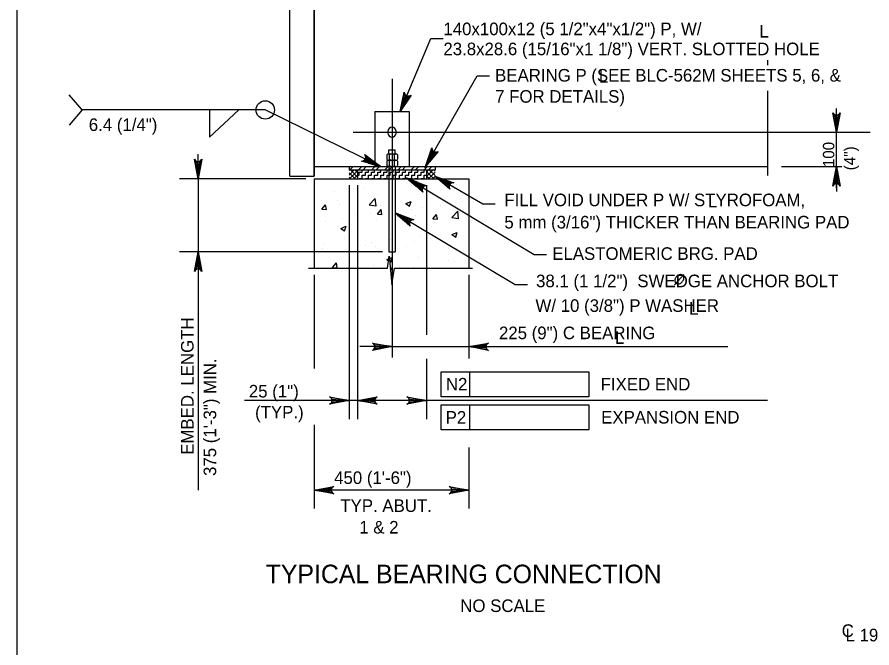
# Model space of a CAD drawing. Extents: x 638263 to 640360, y 293683 to 298655.
# Drawn here: x 639316.5 to 639520.4, y 298195.5 to 298346 of the extents above; entities that cross this region are included whole.
import ezdxf

# ---------------------------------------------------------------- set-up
doc = ezdxf.new("R2010")
doc.units = 0
for name, color, linetype in [('2', 7, 'Continuous'), ('3', 7, 'Continuous'), ('4', 7, 'Continuous'), ('5', 7, 'Continuous')]:
    doc.layers.add(name, color=color, linetype=linetype)

msp = doc.modelspace()

# ---------------------------------------------------------------- linework, layer by layer
at = {"layer": '2'}
msp.add_line((639316.46, 297856.46), (639316.46, 298420.46), dxfattribs=at)
at = {"layer": '3'}
for p, q in [((639407.82, 298323.5), (639415.19, 298340.91)), ((639415.19, 298340.91), (639418.14, 298340.91)), ((639405.92, 298331.32), (639405.92, 298264.85)), ((639413.87, 298310.37), (639426.24, 298332.05)), ((639426.24, 298332.05), (639429.19, 298332.05)), ((639331.95, 298323.89), (639328.89, 298327.5)), ((639511.95, 298305.24), (639511.95, 298324.21)), ((639331.95, 298323.89), (639328.89, 298320.29)), ((639375.66, 298323.89), (639331.95, 298323.89)), ((639362.38, 298317.4), (639369.36, 298323.89)), ((639362.38, 298323.89), (639362.38, 298317.4)), ((639403.19, 298310.38), (639375.66, 298323.89)), ((639396.65, 298318.58), (639520, 298318.58)), ((639359.63, 298307.45), (639359.63, 298313.35)), ((639498.8, 298310.37), (639513.23, 298310.37)), ((639416.6, 298307.82), (639427.55, 298301.49)), ((639385.31, 298307.45), (639355.2, 298307.45)), ((639359.63, 298307.45), (639359.63, 298290)), ((639395.66, 298305.91), (639395.66, 298250.11)), ((639397.71, 298305.91), (639397.71, 298250.11)), ((639409.75, 298307.45), (639439.84, 298289.43)), ((639414.12, 298305.91), (639414.12, 298270.25)), ((639511.95, 298307.42), (639511.95, 298304.47)), ((639427.55, 298301.49), (639430.5, 298301.49)), ((639406.69, 298299.33), (639435.31, 298282.22)), ((639403.61, 298290), (639355.2, 298290)), ((639359.63, 298290), (639359.63, 298233.19)), ((639439.84, 298289.43), (639442.79, 298289.43)), ((639387.33, 298284.56), (639387.33, 298262.23)), ((639424.24, 298284.56), (639424.24, 298264.62)), ((639435.31, 298282.22), (639438.26, 298282.22)), ((639424.24, 298270.92), (639424.24, 298266.05)), ((639401.95, 298267.41), (639398.27, 298267.41)), ((639404.91, 298267.41), (639486.02, 298267.41)), ((639414.12, 298264.48), (639414.12, 298250.11)), ((639417.6, 298261.37), (639424.44, 298261.37)), ((639417.6, 298255.47), (639417.6, 298261.37)), ((639424.44, 298255.47), (639424.44, 298261.37)), ((639424.44, 298261.37), (639452.9, 298261.37)), ((639452.9, 298261.37), (639452.9, 298255.47)), ((639452.9, 298255.47), (639417.6, 298255.47)), ((639495.46, 298254.54), (639370.75, 298254.54)), ((639417.6, 298253.49), (639424.44, 298253.49)), ((639417.6, 298247.59), (639417.6, 298253.49)), ((639424.44, 298247.59), (639424.44, 298253.49)), ((639424.44, 298253.49), (639452.9, 298253.49)), ((639452.9, 298253.49), (639452.9, 298247.59)), ((639387.33, 298248.72), (639387.33, 298228.76)), ((639452.9, 298247.59), (639417.6, 298247.59)), ((639424.24, 298243.36), (639424.24, 298228.76)), ((639424.24, 298233.19), (639387.33, 298233.19))]:
    msp.add_line(p, q, dxfattribs=at)
for points in [[(639407.82, 298323.5), (639408.83, 298328.13), (639408.92, 298327.7), (639409.13, 298327.41), (639409.4, 298327.24), (639409.71, 298327.17), (639410.07, 298327.21), (639410.44, 298327.45), (639407.82, 298323.5), (639410.07, 298327.21), (639409.71, 298327.17), (639407.82, 298323.5), (639409.4, 298327.24), (639409.13, 298327.41), (639407.82, 298323.5), (639408.92, 298327.7)], [(639511.95, 298318.58), (639511.08, 298323.24), (639511.33, 298322.88), (639511.64, 298322.69), (639511.95, 298322.64), (639512.27, 298322.69), (639512.58, 298322.88), (639512.83, 298323.24), (639511.95, 298318.58), (639512.58, 298322.88), (639512.27, 298322.69), (639511.95, 298318.58), (639511.95, 298322.64), (639511.64, 298322.69), (639511.95, 298318.58), (639511.33, 298322.88)], [(639413.87, 298310.37), (639415.42, 298314.86), (639415.46, 298314.42), (639415.64, 298314.1), (639415.88, 298313.9), (639416.18, 298313.8), (639416.54, 298313.8), (639416.94, 298313.99), (639413.87, 298310.37), (639416.54, 298313.8), (639416.18, 298313.8), (639413.87, 298310.37), (639415.88, 298313.9), (639415.64, 298314.1), (639413.87, 298310.37), (639415.46, 298314.42)], [(639359.63, 298307.45), (639358.75, 298312.11), (639359, 298311.75), (639359.31, 298311.56), (639359.63, 298311.51), (639359.94, 298311.56), (639360.25, 298311.75), (639360.5, 298312.11), (639359.63, 298307.45), (639360.25, 298311.75), (639359.94, 298311.56), (639359.63, 298307.45), (639359.63, 298311.51), (639359.31, 298311.56), (639359.63, 298307.45), (639359, 298311.75)], [(639403.19, 298310.38), (639398.62, 298311.65), (639399.05, 298311.71), (639399.36, 298311.91), (639399.54, 298312.17), (639399.63, 298312.47), (639399.6, 298312.83), (639399.39, 298313.22), (639403.19, 298310.38), (639399.6, 298312.83), (639399.63, 298312.47), (639403.19, 298310.38), (639399.54, 298312.17), (639399.36, 298311.91), (639403.19, 298310.38), (639399.05, 298311.71)], [(639511.95, 298310.37), (639512.83, 298305.71), (639512.58, 298306.07), (639512.27, 298306.26), (639511.95, 298306.31), (639511.64, 298306.26), (639511.33, 298306.07), (639511.08, 298305.71), (639511.95, 298310.37), (639511.33, 298306.07), (639511.64, 298306.26), (639511.95, 298310.37), (639511.95, 298306.31), (639512.27, 298306.26), (639511.95, 298310.37), (639512.58, 298306.07)], [(639416.15, 298308.08), (639420.62, 298306.5), (639420.18, 298306.47), (639419.87, 298306.29), (639419.66, 298306.05), (639419.55, 298305.75), (639419.56, 298305.38), (639419.74, 298304.99), (639416.15, 298308.08), (639419.56, 298305.38), (639419.55, 298305.75), (639416.15, 298308.08), (639419.66, 298306.05), (639419.87, 298306.29), (639416.15, 298308.08), (639420.18, 298306.47)], [(639409.75, 298307.45), (639414.2, 298305.8), (639413.76, 298305.77), (639413.45, 298305.6), (639413.24, 298305.36), (639413.12, 298305.06), (639413.12, 298304.7), (639413.3, 298304.3), (639409.75, 298307.45), (639413.12, 298304.7), (639413.12, 298305.06), (639409.75, 298307.45), (639413.24, 298305.36), (639413.45, 298305.6), (639409.75, 298307.45), (639413.76, 298305.77)], [(639406.69, 298299.33), (639411.13, 298297.68), (639410.7, 298297.66), (639410.38, 298297.48), (639410.17, 298297.24), (639410.06, 298296.95), (639410.06, 298296.58), (639410.24, 298296.18), (639406.69, 298299.33), (639410.06, 298296.58), (639410.06, 298296.95), (639406.69, 298299.33), (639410.17, 298297.24), (639410.38, 298297.48), (639406.69, 298299.33), (639410.7, 298297.66)], [(639359.63, 298290), (639360.5, 298285.34), (639360.25, 298285.7), (639359.94, 298285.88), (639359.63, 298285.94), (639359.31, 298285.88), (639359, 298285.7), (639358.75, 298285.34), (639359.63, 298290), (639359, 298285.7), (639359.31, 298285.88), (639359.63, 298290), (639359.63, 298285.94), (639359.94, 298285.88), (639359.63, 298290), (639360.25, 298285.7)], [(639405.92, 298267.41), (639401.26, 298266.53), (639401.61, 298266.78), (639401.8, 298267.1), (639401.85, 298267.41), (639401.8, 298267.72), (639401.61, 298268.03), (639401.26, 298268.28), (639405.92, 298267.41), (639401.61, 298268.03), (639401.8, 298267.72), (639405.92, 298267.41), (639401.85, 298267.41), (639401.8, 298267.1), (639405.92, 298267.41), (639401.61, 298266.78)], [(639424.24, 298267.41), (639428.9, 298268.28), (639428.54, 298268.03), (639428.36, 298267.72), (639428.3, 298267.41), (639428.36, 298267.1), (639428.54, 298266.78), (639428.9, 298266.53), (639424.24, 298267.41), (639428.54, 298266.78), (639428.36, 298267.1), (639424.24, 298267.41), (639428.3, 298267.41), (639428.36, 298267.72), (639424.24, 298267.41), (639428.54, 298268.03)], [(639395.66, 298254.54), (639391, 298253.67), (639391.36, 298253.91), (639391.55, 298254.23), (639391.6, 298254.54), (639391.55, 298254.85), (639391.36, 298255.16), (639391, 298255.41), (639395.66, 298254.54), (639391.36, 298255.16), (639391.55, 298254.85), (639395.66, 298254.54), (639391.6, 298254.54), (639391.55, 298254.23), (639395.66, 298254.54), (639391.36, 298253.91)], [(639397.71, 298254.54), (639402.37, 298255.41), (639402.02, 298255.16), (639401.83, 298254.85), (639401.78, 298254.54), (639401.83, 298254.23), (639402.02, 298253.91), (639402.37, 298253.67), (639397.71, 298254.54), (639402.02, 298253.91), (639401.83, 298254.23), (639397.71, 298254.54), (639401.78, 298254.54), (639401.83, 298254.85), (639397.71, 298254.54), (639402.02, 298255.16)], [(639414.12, 298254.54), (639409.46, 298253.67), (639409.82, 298253.91), (639410, 298254.23), (639410.06, 298254.54), (639410, 298254.85), (639409.82, 298255.16), (639409.46, 298255.41), (639414.12, 298254.54), (639409.82, 298255.16), (639410, 298254.85), (639414.12, 298254.54), (639410.06, 298254.54), (639410, 298254.23), (639414.12, 298254.54), (639409.82, 298253.91)], [(639387.33, 298233.19), (639391.99, 298234.06), (639391.63, 298233.82), (639391.44, 298233.5), (639391.39, 298233.19), (639391.44, 298232.88), (639391.63, 298232.57), (639391.99, 298232.32), (639387.33, 298233.19), (639391.63, 298232.57), (639391.44, 298232.88), (639387.33, 298233.19), (639391.39, 298233.19), (639391.44, 298233.5), (639387.33, 298233.19), (639391.63, 298233.82)], [(639424.24, 298233.19), (639419.58, 298232.32), (639419.94, 298232.57), (639420.12, 298232.88), (639420.18, 298233.19), (639420.12, 298233.5), (639419.94, 298233.82), (639419.58, 298234.06), (639424.24, 298233.19), (639419.94, 298233.82), (639420.12, 298233.5), (639424.24, 298233.19), (639420.18, 298233.19), (639420.12, 298232.88), (639424.24, 298233.19), (639419.94, 298232.57)]]:
    msp.add_lwpolyline(points, dxfattribs=at)
for points in [[(639409.42, 298326.02), (639408.51, 298326.41), (639407.82, 298323.5)], [(639400.76, 298312.12), (639400.33, 298311.23), (639403.2, 298310.37)], [(639415.6, 298312.42), (639414.75, 298312.9), (639413.71, 298310.1)], [(639359.13, 298310.4), (639360.12, 298310.4), (639359.63, 298307.45)], [(639411.66, 298305.73), (639412.17, 298306.57), (639409.38, 298307.67)], [(639408.97, 298297.39), (639409.47, 298298.23), (639406.69, 298299.33)], [(639359.13, 298287.05), (639360.12, 298287.05), (639359.63, 298290)], [(639427.19, 298267.9), (639427.19, 298266.92), (639424.24, 298267.41)]]:
    msp.add_lwpolyline(points, close=True, dxfattribs=at)
msp.add_circle((639375.66, 298323.89), 2.19, dxfattribs=at)
at = {"layer": '4'}
msp.add_line((639473.32, 298282.17), (639475.56, 298284.63), dxfattribs=at)
msp.add_spline([(639475.32, 298284.38), (639475.15, 298284.52), (639474.97, 298284.57), (639474.76, 298284.59), (639474.63, 298284.59), (639474.41, 298284.54), (639474.21, 298284.45), (639474.08, 298284.37), (639473.81, 298284.16), (639473.61, 298283.89), (639473.48, 298283.64), (639473.41, 298283.41), (639473.39, 298283.19), (639473.41, 298283.01), (639473.5, 298282.74), (639473.6, 298282.61), (639473.79, 298282.46), (639474.07, 298282.39), (639474.41, 298282.4), (639474.82, 298282.59), (639475.13, 298282.85), (639475.36, 298283.17), (639475.51, 298283.5), (639475.56, 298283.87), (639475.49, 298284.11), (639475.34, 298284.38)], degree=3, dxfattribs=at)
at = {"layer": '5'}
for p, q in [((639381.56, 298308.06), (639381.56, 298385.48)), ((639387.33, 298308.06), (639387.33, 298385.48)), ((639387.33, 298378.04), (639387.33, 298308.06)), ((639495.53, 298335.78), (639495.53, 298334.59)), ((639495.53, 298328.49), (639495.53, 298308.28)), ((639401.84, 298323.5), (639410, 298323.5)), ((639401.84, 298323.5), (639401.84, 298310.37)), ((639410, 298323.5), (639410, 298310.37)), ((639404.94, 298318.77), (639404.94, 298318.38)), ((639406.89, 298318.77), (639406.89, 298318.38)), ((639405.15, 298313.4), (639405.15, 298314.38)), ((639405.15, 298314.38), (639406.69, 298314.38)), ((639406.69, 298313.4), (639406.69, 298314.38)), ((639404.69, 298313.18), (639404.69, 298312.11)), ((639404.98, 298313.4), (639406.87, 298313.4)), ((639404.98, 298311.89), (639406.87, 298311.89)), ((639404.98, 298311.88), (639406.87, 298311.88)), ((639405.15, 298311.89), (639406.69, 298311.89)), ((639405.29, 298312.11), (639405.29, 298313.18)), ((639406.54, 298312.11), (639406.54, 298313.18)), ((639407.19, 298313.18), (639407.19, 298312.11)), ((639387.33, 298310.37), (639424.24, 298310.37)), ((639395.66, 298310.37), (639395.66, 298309.61)), ((639395.86, 298309.61), (639396.63, 298310.37)), ((639397.95, 298309.61), (639398.72, 298310.37)), ((639398.99, 298309.61), (639399.76, 298310.37)), ((639401.08, 298309.61), (639401.85, 298310.37)), ((639402.13, 298309.61), (639402.9, 298310.37)), ((639404.21, 298309.61), (639404.99, 298310.37)), ((639404.69, 298311.67), (639404.69, 298310.6)), ((639404.98, 298310.37), (639406.87, 298310.37)), ((639405.15, 298310.37), (639406.69, 298310.37)), ((639405.15, 298310.37), (639405.15, 298290)), ((639405.26, 298309.61), (639406.03, 298310.37)), ((639405.29, 298310.6), (639405.29, 298311.67)), ((639406.54, 298310.6), (639406.54, 298311.67)), ((639406.69, 298310.37), (639406.69, 298290)), ((639407.19, 298311.67), (639407.19, 298310.6)), ((639407.35, 298309.61), (639408.12, 298310.37)), ((639408.39, 298309.61), (639409.16, 298310.37)), ((639410.48, 298309.61), (639411.25, 298310.37)), ((639411.52, 298309.61), (639412.29, 298310.37)), ((639413.61, 298309.61), (639414.38, 298310.37)), ((639414.65, 298309.61), (639415.42, 298310.37)), ((639416.17, 298310.37), (639416.17, 298309.61)), ((639424.24, 298310.37), (639495.53, 298310.37)), ((639381.56, 298308.06), (639387.33, 298308.06)), ((639395.66, 298309.61), (639416.17, 298309.61)), ((639395.66, 298308.36), (639396.91, 298309.61)), ((639395.66, 298309.41), (639395.86, 298309.61)), ((639397.11, 298307.45), (639395.66, 298308.89)), ((639396.07, 298307.45), (639395.66, 298307.85)), ((639395.79, 298307.45), (639397.71, 298309.37)), ((639397.71, 298307.89), (639396, 298309.61)), ((639396.83, 298307.45), (639397.71, 298308.32)), ((639397.71, 298308.93), (639397.04, 298309.61)), ((639397.71, 298309.61), (639397.71, 298307.45)), ((639397.71, 298308.31), (639398.08, 298308.31)), ((639398.08, 298309.05), (639398.81, 298309.05)), ((639398.08, 298308.31), (639398.08, 298309.05)), ((639398.81, 298309.05), (639398.81, 298309.61)), ((639398.81, 298308.31), (639399.55, 298308.31)), ((639398.81, 298307.57), (639398.81, 298308.31)), ((639399.55, 298309.05), (639400.29, 298309.05)), ((639399.55, 298308.31), (639399.55, 298309.05)), ((639400.29, 298309.05), (639400.29, 298309.61)), ((639400.29, 298308.31), (639401.03, 298308.31)), ((639400.29, 298307.57), (639400.29, 298308.31)), ((639401.03, 298309.05), (639401.77, 298309.05)), ((639401.03, 298308.31), (639401.03, 298309.05)), ((639401.77, 298309.05), (639401.77, 298309.61)), ((639401.77, 298308.31), (639402.51, 298308.31)), ((639401.77, 298307.57), (639401.77, 298308.31)), ((639402.51, 298309.05), (639403.24, 298309.05)), ((639402.51, 298308.31), (639402.51, 298309.05)), ((639403.24, 298309.05), (639403.24, 298309.61)), ((639403.24, 298308.31), (639403.98, 298308.31)), ((639403.24, 298307.57), (639403.24, 298308.31)), ((639403.98, 298309.05), (639404.72, 298309.05)), ((639403.98, 298308.31), (639403.98, 298309.05)), ((639404.72, 298309.05), (639404.72, 298309.61)), ((639404.72, 298308.31), (639405.15, 298308.31)), ((639404.72, 298307.57), (639404.72, 298308.31)), ((639405.15, 298308.31), (639405.46, 298308.31)), ((639405.46, 298309.05), (639405.92, 298309.05)), ((639405.46, 298308.31), (639405.46, 298309.05)), ((639405.92, 298309.05), (639406.2, 298309.05)), ((639406.2, 298309.05), (639406.2, 298309.61)), ((639406.2, 298308.31), (639406.69, 298308.31)), ((639406.2, 298307.57), (639406.2, 298308.31)), ((639406.69, 298308.31), (639406.94, 298308.31)), ((639406.94, 298309.05), (639407.67, 298309.05)), ((639406.94, 298308.31), (639406.94, 298309.05)), ((639407.67, 298309.05), (639407.67, 298309.61)), ((639407.67, 298308.31), (639408.41, 298308.31)), ((639407.67, 298307.57), (639407.67, 298308.31)), ((639408.41, 298309.05), (639409.15, 298309.05)), ((639408.41, 298308.31), (639408.41, 298309.05)), ((639409.15, 298309.05), (639409.15, 298309.61)), ((639409.15, 298308.31), (639409.89, 298308.31)), ((639409.15, 298307.57), (639409.15, 298308.31)), ((639409.89, 298309.05), (639410.63, 298309.05)), ((639409.89, 298308.31), (639409.89, 298309.05)), ((639410.63, 298309.05), (639410.63, 298309.61)), ((639410.63, 298308.31), (639411.36, 298308.31)), ((639410.63, 298307.57), (639410.63, 298308.31)), ((639411.36, 298309.05), (639412.1, 298309.05)), ((639411.36, 298308.31), (639411.36, 298309.05)), ((639412.1, 298309.05), (639412.1, 298309.61)), ((639412.1, 298308.31), (639412.84, 298308.31)), ((639412.1, 298307.57), (639412.1, 298308.31)), ((639412.84, 298309.05), (639413.58, 298309.05)), ((639412.84, 298308.31), (639412.84, 298309.05)), ((639413.58, 298309.05), (639413.58, 298309.61)), ((639413.58, 298308.31), (639414.12, 298308.31)), ((639413.58, 298307.57), (639413.58, 298308.31)), ((639414.12, 298309.61), (639414.12, 298307.45)), ((639414.12, 298309.07), (639414.65, 298309.61)), ((639414.12, 298308.03), (639415.7, 298309.61)), ((639415.9, 298307.45), (639414.12, 298309.23)), ((639414.86, 298307.45), (639414.12, 298308.18)), ((639414.58, 298307.45), (639416.17, 298309.03)), ((639416.17, 298308.22), (639414.79, 298309.61)), ((639415.62, 298307.45), (639416.17, 298307.99)), ((639416.17, 298309.27), (639415.83, 298309.61)), ((639387.33, 298307.45), (639424.24, 298307.45)), ((639387.33, 298307.45), (639387.33, 298286.1)), ((639398.08, 298307.57), (639398.81, 298307.57)), ((639398.08, 298307.45), (639398.08, 298307.57)), ((639399.55, 298307.57), (639400.29, 298307.57)), ((639399.55, 298307.45), (639399.55, 298307.57)), ((639401.03, 298307.57), (639401.77, 298307.57)), ((639401.03, 298307.45), (639401.03, 298307.57)), ((639402.51, 298307.57), (639403.24, 298307.57)), ((639402.51, 298307.45), (639402.51, 298307.57)), ((639403.98, 298307.57), (639404.72, 298307.57)), ((639403.98, 298307.45), (639403.98, 298307.57)), ((639405.46, 298307.57), (639405.92, 298307.57)), ((639405.46, 298307.45), (639405.46, 298307.57)), ((639405.92, 298307.57), (639406.2, 298307.57)), ((639406.94, 298307.57), (639407.67, 298307.57)), ((639406.94, 298307.45), (639406.94, 298307.57)), ((639408.41, 298307.57), (639409.15, 298307.57)), ((639408.41, 298307.45), (639408.41, 298307.57)), ((639409.89, 298307.57), (639410.63, 298307.57)), ((639409.89, 298307.45), (639409.89, 298307.57)), ((639410.72, 298306.83), (639410.72, 298306.83)), ((639411.36, 298307.57), (639412.1, 298307.57)), ((639411.36, 298307.45), (639411.36, 298307.57)), ((639412.84, 298307.57), (639413.58, 298307.57)), ((639412.84, 298307.45), (639412.84, 298307.57)), ((639415.34, 298307.44), (639415.34, 298307.44)), ((639421.4, 298306.2), (639421.4, 298306.2)), ((639424.24, 298307.45), (639424.24, 298286.1)), ((639387.46, 298303.77), (639387.46, 298303.77)), ((639392.08, 298304.38), (639392.08, 298304.38)), ((639399.07, 298305.3), (639399.07, 298305.3)), ((639411.82, 298304.81), (639411.82, 298304.81)), ((639393.02, 298302.33), (639393.02, 298302.33)), ((639400.46, 298301.26), (639401.9, 298302.76)), ((639402.1, 298301.01), (639401.9, 298302.76)), ((639402.5, 298303.63), (639402.5, 298303.63)), ((639409.17, 298301.58), (639410.46, 298302.07)), ((639410.09, 298300.96), (639410.46, 298302.07)), ((639422.35, 298302.82), (639422.35, 298302.82)), ((639389.18, 298300.21), (639390.07, 298301.27)), ((639389.18, 298300.21), (639390.28, 298300.11)), ((639390.28, 298300.11), (639390.07, 298301.27)), ((639393.39, 298301.42), (639393.39, 298301.42)), ((639400.46, 298301.26), (639402.1, 298301.01)), ((639402.42, 298299.05), (639403.31, 298300.11)), ((639403.24, 298301.01), (639403.24, 298301.01)), ((639403.52, 298298.95), (639403.31, 298300.11)), ((639409.17, 298301.58), (639410.09, 298300.96)), ((639410.49, 298300.16), (639410.49, 298300.16)), ((639411.59, 298300.98), (639411.59, 298300.98)), ((639413.09, 298300.59), (639413.09, 298300.59)), ((639417.48, 298301.08), (639417.48, 298301.08)), ((639420.16, 298298.21), (639421.6, 298299.71)), ((639421.18, 298300.05), (639421.18, 298300.05)), ((639421.8, 298297.95), (639421.6, 298299.71)), ((639422.95, 298300.17), (639422.95, 298300.17)), ((639387.43, 298299.36), (639387.43, 298299.36)), ((639394.21, 298298.02), (639394.21, 298298.02)), ((639397.28, 298298.95), (639397.28, 298298.95)), ((639400.83, 298299.13), (639400.83, 298299.13)), ((639402.42, 298299.05), (639403.52, 298298.95)), ((639405.87, 298299.55), (639405.87, 298299.55)), ((639407.13, 298298.53), (639407.13, 298298.53)), ((639411.6, 298298.67), (639411.6, 298298.67)), ((639415.65, 298297.89), (639416.54, 298298.95)), ((639415.65, 298297.89), (639416.76, 298297.79)), ((639416.76, 298297.79), (639416.54, 298298.95)), ((639416.99, 298298.11), (639416.99, 298298.11)), ((639420.16, 298298.21), (639421.8, 298297.95)), ((639390.07, 298297.28), (639390.07, 298297.28)), ((639392.8, 298296.19), (639392.8, 298296.19)), ((639393.66, 298295.63), (639394.96, 298296.12)), ((639393.66, 298295.63), (639394.58, 298295.01)), ((639394.58, 298295.01), (639394.96, 298296.12)), ((639402.27, 298297.49), (639402.27, 298297.49)), ((639416.01, 298296.92), (639416.01, 298296.92)), ((639405.25, 298295.08), (639405.25, 298295.08)), ((639412.62, 298293.8), (639412.62, 298293.8)), ((639420.19, 298294.15), (639421.48, 298294.65)), ((639420.19, 298294.15), (639421.1, 298293.53)), ((639420.96, 298293.91), (639420.96, 298293.91)), ((639421.1, 298293.53), (639421.48, 298294.65)), ((639389.72, 298292.04), (639389.72, 298292.04)), ((639394.49, 298293.23), (639394.49, 298293.23)), ((639399.57, 298291.63), (639399.57, 298291.63)), ((639401.01, 298292.27), (639401.01, 298292.27)), ((639405.63, 298292.88), (639405.63, 298292.88)), ((639411.37, 298292.52), (639411.37, 298292.52)), ((639389.36, 298290.74), (639389.36, 298290.74)), ((639392.57, 298290.04), (639392.57, 298290.04)), ((639402.05, 298291.34), (639402.05, 298291.34)), ((639405.15, 298290), (639406.69, 298290)), ((639409.42, 298291.21), (639409.42, 298291.21)), ((639419.27, 298290.79), (639419.27, 298290.79)), ((639423.06, 298290.47), (639423.06, 298290.47)), ((639404.68, 298288.2), (639405.18, 298288.39)), ((639404.68, 298288.2), (639405.1, 298287.91)), ((639404.82, 298286.1), (639405.27, 298289)), ((639405.27, 298289), (639405.86, 298282.24)), ((639405.32, 298288.44), (639405.97, 298288.69)), ((639405.39, 298287.72), (639405.6, 298287.58)), ((639405.6, 298287.58), (639405.97, 298288.69)), ((639412.3, 298288.62), (639412.3, 298288.62)), ((639419.42, 298288.06), (639419.42, 298288.06)), ((639420.73, 298287.76), (639420.73, 298287.76)), ((639424.04, 298288.67), (639424.04, 298288.67)), ((639386.01, 298286.1), (639404.82, 298286.1)), ((639391.74, 298286.32), (639392.63, 298287.38)), ((639391.74, 298286.32), (639392.84, 298286.23)), ((639392.84, 298286.23), (639392.63, 298287.38)), ((639401.54, 298286.77), (639401.54, 298286.77)), ((639405.55, 298285.85), (639405.87, 298286.23)), ((639405.86, 298282.24), (639406.48, 298286.1)), ((639406.08, 298285.07), (639405.87, 298286.23)), ((639406.48, 298286.1), (639425.13, 298286.1)), ((639407.77, 298286.52), (639407.77, 298286.52)), ((639411.15, 298286.38), (639411.15, 298286.38)), ((639405.61, 298285.11), (639406.08, 298285.07))]:
    msp.add_line(p, q, dxfattribs=at)
for centre, radius, start, end in [((639405.92, 298318.77), 0.976, 0, 180), ((639405.92, 298318.38), 0.976, 180, 0), ((639404.99, 298313.08), 0.316, 17.4518, 162.5482), ((639404.99, 298312.2), 0.316, 197.4518, 342.5482), ((639404.99, 298311.57), 0.316, 17.4518, 162.5482), ((639405.92, 298312.41), 0.994, 51.05, 128.95), ((639405.92, 298312.88), 0.994, 231.05, 308.95), ((639405.92, 298310.89), 0.994, 51.05, 128.95), ((639406.86, 298313.05), 0.347, 91.8271, 158.7131), ((639406.86, 298312.23), 0.347, 201.2869, 268.1729), ((639406.86, 298311.54), 0.347, 91.8271, 158.7131), ((639406.86, 298313.05), 0.347, 21.2869, 91.8271), ((639406.86, 298312.23), 0.347, 268.1729, 338.7131), ((639406.86, 298311.54), 0.347, 21.2869, 91.8271), ((639404.99, 298310.69), 0.316, 197.4518, 342.5482), ((639405.92, 298311.37), 0.994, 231.05, 308.95), ((639406.86, 298310.72), 0.347, 201.2869, 268.1729), ((639406.86, 298310.72), 0.347, 268.1729, 338.7131)]:
    msp.add_arc(centre, radius, start, end, dxfattribs=at)

# ---------------------------------------------------------------- texts
at = {"layer": '3'}
for s, height, p in [('BEARING P (SEE BLC-562M SHEETS 5, 6, & ', 3, (639430.51, 298330.66)), ('L', 3, (639455.26, 298330.36)), ('7 FOR DETAILS)', 3, (639430.51, 298325.62)), ('FILL VOID UNDER P W/ STYROFOAM,', 3, (639432.72, 298300.92)), ('L', 3, (639481.26, 298300.67)), ('5 mm (3/16") THICKER THAN BEARING PAD', 3, (639432.72, 298295.61)), ('ELASTOMERIC BRG. PAD', 3, (639444.14, 298288.12)), ('38.1 (1 1/2")  SWEDGE ANCHOR BOLT', 3, (639440.28, 298281.59)), ('W/ 10 (3/8") P WASHER', 3, (639440.14, 298275.71)), ('L', 3, (639476.79, 298275.03)), ('225 (9") C BEARING', 3, (639431.43, 298269.19)), ('L', 3, (639459.12, 298268.08)), ('N2', 3, (639418.76, 298256.95)), ('FIXED END', 3, (639455.69, 298256.95)), ('25 (1")', 3, (639371.75, 298255.28)), ('(TYP.)', 3, (639373.24, 298250.28)), ('P2', 3, (639418.71, 298249.03)), ('EXPANSION END', 3, (639455.81, 298249.07)), ('450 (1\'-6")', 3, (639392.1, 298234.64)), ('TYP. ABUT.', 3, (639393.58, 298227.97)), ('1 & 2', 3, (639398.1, 298222.82)), ('TYPICAL BEARING CONNECTION', 4.4292, (639375.78, 298210.96)), ('NO SCALE', 3, (639422.2, 298204.09)), ('C', 3, (639513.2, 298198.15)), ('L 19.1 (3/4")  LAG SCREW (LENGTH OF LAG SCREW = 175 (7")+ BEAM WIDTH)', 3, (639514.12, 298197.09))]:
    msp.add_text(s, height=height, dxfattribs=at).set_placement(p)
for s, height, p in [('100', 2.708, (639511.43, 298310.23)), ('(4")', 2.708, (639516.49, 298309.49)), ('EMBED. LENGTH', 3, (639358.57, 298241.61)), ('375 (1\'-3") MIN.', 3, (639363.96, 298236.55))]:
    msp.add_text(s, height=height, rotation=90, dxfattribs=at).set_placement(p)
at = {"layer": '4'}
for s, p in [('140x100x12 (5 1/2"x4"x1/2") P, W/', (639418.17, 298341.73)), ('L', (639493.56, 298341.17)), ('23.8x28.6 (15/16"x1 1/8") VERT. SLOTTED HOLE', (639418.17, 298336.95)), ('6.4 (1/4")', (639333.56, 298318.87))]:
    msp.add_text(s, height=3, dxfattribs=at).set_placement(p)

doc.saveas('drawing.dxf')
